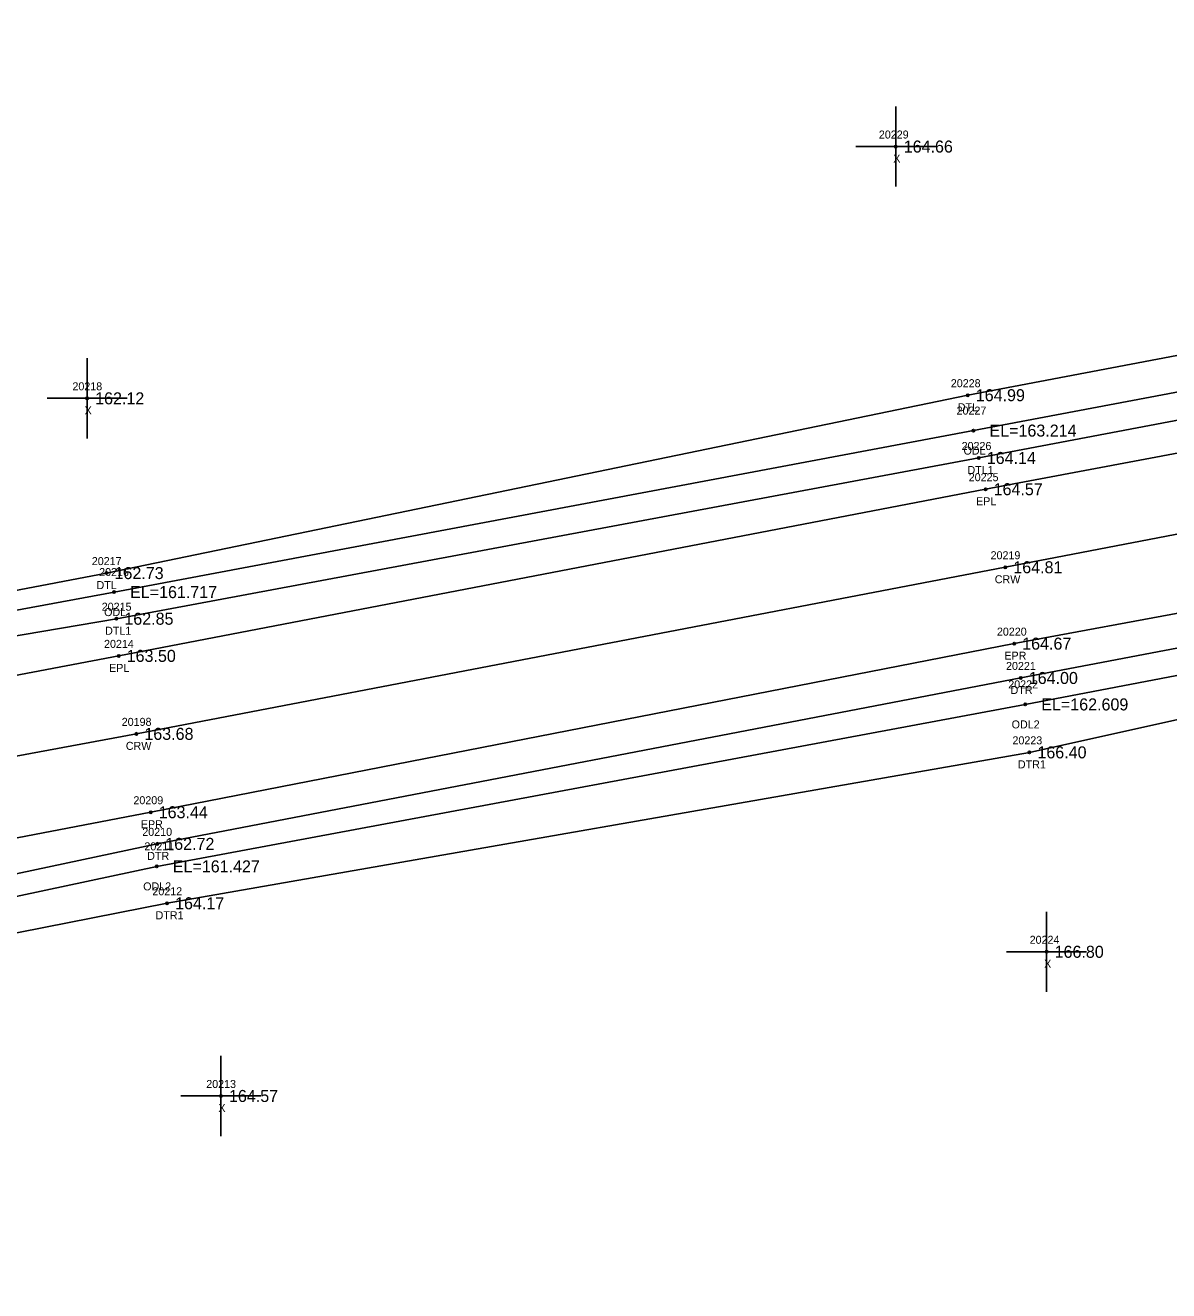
# Model space of a CAD drawing. Extents: x 2381545 to 2382928, y 1029933 to 1030589.
# Drawn here: x 2382543.8 to 2382686.7, y 1030367.7 to 1030525.8 of the extents above; entities that cross this region are included whole.
import ezdxf

# ---------------------------------------------------------------- set-up
doc = ezdxf.new("R2010")
doc.units = 0
for name, color, linetype in [('RD_DTM_BkLn1', 7, 'Continuous'), ('RD_EX_H2O', 7, 'Continuous'), ('RD_EX_H2O_txCode', 7, 'Continuous'), ('RD_EX_Misc', 7, 'Continuous'), ('RD_EX_Misc_txCode', 7, 'Continuous'), ('RD_EX_Road', 7, 'Continuous'), ('RD_EX_Road_txCode', 7, 'Continuous'), ('RD_EX_TX_H2O_ELEV', 7, 'Continuous'), ('RD_EX_TX_Misc_ELEV', 7, 'Continuous'), ('RD_EX_TX_Road_ELEV', 7, 'Continuous'), ('RD_HC_Survey_ELEV', 7, 'Continuous'), ('RD_HC_Survey_txCode', 7, 'Continuous'), ('RD_SMD_Locator', 7, 'Continuous')]:
    doc.layers.add(name, color=color, linetype=linetype)

msp = doc.modelspace()

# ---------------------------------------------------------------- linework, layer by layer
at = {"layer": 'RD_DTM_BkLn1'}
msp.add_lwpolyline([(2382237.83, 1030377.97), (2382343.9, 1030397.77), (2382436.97, 1030414.87), (2382557.72, 1030437.27), (2382666.29, 1030458.08), (2382780.92, 1030480.13), (2382908.6, 1030503.95)], dxfattribs=at)
at = {"layer": 'RD_EX_H2O'}
for points in [[(2382466.62, 1030439.12), (2382470.56, 1030441.45), (2382553.99, 1030457.35), (2382661.6, 1030479.57), (2382777.69, 1030501.62), (2382905.21, 1030525.77)], [(2382466.62, 1030439.12), (2382471.06, 1030439.47), (2382554.93, 1030454.98), (2382662.31, 1030475.15), (2382778.18, 1030497.02), (2382905.16, 1030521.52)], [(2382466.62, 1030439.12), (2382471.74, 1030437.5), (2382555.22, 1030451.65), (2382662.97, 1030471.73), (2382778.37, 1030493.62), (2382905.48, 1030518.64)], [(2382424.24, 1030390.04), (2382440.08, 1030397.96), (2382560.33, 1030423.53), (2382668.22, 1030444.25), (2382764.75, 1030462.61), (2382766.55, 1030456.54)], [(2382424.24, 1030390.04), (2382440.69, 1030395.22), (2382560.27, 1030420.72), (2382668.78, 1030440.95), (2382763.32, 1030459.02)], [(2382424.24, 1030390.04), (2382441.2, 1030392.41), (2382561.56, 1030416.11), (2382669.3, 1030434.96), (2382766.55, 1030456.54)]]:
    msp.add_lwpolyline(points, dxfattribs=at)
at = {"layer": 'RD_EX_Misc'}
for p, q in [((2382652.6, 1030505.63), (2382652.6, 1030515.63)), ((2382647.6, 1030510.63), (2382657.6, 1030510.63)), ((2382551.57, 1030474.18), (2382551.57, 1030484.18)), ((2382546.57, 1030479.18), (2382556.57, 1030479.18)), ((2382671.45, 1030405.05), (2382671.45, 1030415.05)), ((2382666.45, 1030410.05), (2382676.45, 1030410.05)), ((2382568.29, 1030387.04), (2382568.29, 1030397.04)), ((2382563.29, 1030392.04), (2382573.29, 1030392.04))]:
    msp.add_line(p, q, dxfattribs=at)
at = {"layer": 'RD_EX_Road'}
for points in [[(2382237.83, 1030377.97), (2382235.13, 1030386.42), (2382342.38, 1030406.92), (2382435.08, 1030424.16), (2382555.51, 1030447.01), (2382663.83, 1030467.83), (2382778.84, 1030489.45), (2382906.57, 1030513.81)], [(2382237.83, 1030377.97), (2382241.1, 1030367.72), (2382346.41, 1030388.08), (2382437.98, 1030404.17), (2382559.51, 1030427.48), (2382667.4, 1030448.54), (2382782.14, 1030469.8), (2382910.48, 1030494.44)]]:
    msp.add_lwpolyline(points, dxfattribs=at)
at = {"layer": 'RD_SMD_Locator'}
for centre in [(2382652.6, 1030510.63), (2382551.57, 1030479.18), (2382661.6, 1030479.57), (2382662.31, 1030475.15), (2382662.97, 1030471.73), (2382663.83, 1030467.83), (2382553.99, 1030457.35), (2382666.29, 1030458.08), (2382554.93, 1030454.98), (2382555.22, 1030451.65), (2382667.4, 1030448.54), (2382555.51, 1030447.01), (2382668.22, 1030444.25), (2382668.78, 1030440.95), (2382557.72, 1030437.27), (2382669.3, 1030434.96), (2382559.51, 1030427.48), (2382560.33, 1030423.53), (2382560.27, 1030420.72), (2382561.56, 1030416.11), (2382671.45, 1030410.05), (2382568.29, 1030392.04)]:
    msp.add_circle(centre, 0.15, dxfattribs=at)

# ---------------------------------------------------------------- texts
at = {"layer": 'RD_EX_H2O_txCode'}
for s, p in [('20228', (2382659.48, 1030480.57)), ('20227', (2382660.2, 1030477.15)), ('DTL', (2382660.35, 1030477.57)), ('20226', (2382660.83, 1030472.73)), ('ODL', (2382661.07, 1030472.15)), ('DTL1', (2382661.56, 1030469.73)), ('20217', (2382552.15, 1030458.35)), ('20216', (2382553.07, 1030456.98)), ('DTL', (2382552.74, 1030455.35)), ('20215', (2382553.39, 1030452.65)), ('ODL', (2382553.69, 1030451.98)), ('DTL1', (2382553.81, 1030449.65)), ('20221', (2382666.38, 1030445.25)), ('20222', (2382666.66, 1030442.95)), ('DTR', (2382666.95, 1030442.25)), ('ODL2', (2382667.08, 1030437.95)), ('20223', (2382667.18, 1030435.96)), ('DTR1', (2382667.86, 1030432.96)), ('20210', (2382558.46, 1030424.53)), ('20211', (2382558.72, 1030422.72)), ('DTR', (2382559.07, 1030421.53)), ('ODL2', (2382558.57, 1030417.72)), ('20212', (2382559.72, 1030417.11)), ('DTR1', (2382560.12, 1030414.11))]:
    msp.add_text(s, height=1, dxfattribs=at).set_placement(p)
at = {"layer": 'RD_EX_Misc_txCode'}
for s, p in [('20229', (2382650.49, 1030511.63)), ('X', (2382652.29, 1030508.63)), ('20218', (2382549.73, 1030480.18)), ('X', (2382551.25, 1030477.18)), ('20224', (2382669.33, 1030411.05)), ('X', (2382671.14, 1030408.05)), ('20213', (2382566.45, 1030393.04)), ('X', (2382567.97, 1030390.04))]:
    msp.add_text(s, height=1, dxfattribs=at).set_placement(p)
at = {"layer": 'RD_EX_Road_txCode'}
for s, p in [('20225', (2382661.72, 1030468.83)), ('EPL', (2382662.63, 1030465.83)), ('20220', (2382665.24, 1030449.54)), ('20214', (2382553.68, 1030448.01)), ('EPR', (2382666.17, 1030446.54)), ('EPL', (2382554.31, 1030445.01)), ('20209', (2382557.35, 1030428.48)), ('EPR', (2382558.28, 1030425.48))]:
    msp.add_text(s, height=1, dxfattribs=at).set_placement(p)
at = {"layer": 'RD_EX_TX_H2O_ELEV'}
for s, p in [('164.99', (2382662.6, 1030478.82)), ('EL=163.214', (2382664.31, 1030474.4)), ('164.14', (2382663.97, 1030470.98)), ('162.73', (2382554.99, 1030456.6)), ('EL=161.717', (2382556.93, 1030454.23)), ('162.85', (2382556.22, 1030450.9)), ('164.00', (2382669.22, 1030443.5)), ('EL=162.609', (2382670.78, 1030440.2)), ('166.40', (2382670.3, 1030434.21)), ('162.72', (2382561.33, 1030422.78)), ('EL=161.427', (2382562.27, 1030419.97)), ('164.17', (2382562.56, 1030415.36))]:
    msp.add_text(s, height=1.5, dxfattribs=at).set_placement(p)
at = {"layer": 'RD_EX_TX_Misc_ELEV'}
for s, p in [('164.66', (2382653.6, 1030509.88)), ('162.12', (2382552.57, 1030478.43)), ('166.80', (2382672.45, 1030409.3)), ('164.57', (2382569.29, 1030391.29))]:
    msp.add_text(s, height=1.5, dxfattribs=at).set_placement(p)
at = {"layer": 'RD_EX_TX_Road_ELEV'}
for s, p in [('164.57', (2382664.83, 1030467.08)), ('164.67', (2382668.4, 1030447.79)), ('163.50', (2382556.51, 1030446.26)), ('163.44', (2382560.51, 1030426.73))]:
    msp.add_text(s, height=1.5, dxfattribs=at).set_placement(p)
at = {"layer": 'RD_HC_Survey_ELEV'}
for s, p in [('164.81', (2382667.29, 1030457.33)), ('163.68', (2382558.72, 1030436.52))]:
    msp.add_text(s, height=1.5, dxfattribs=at).set_placement(p)
at = {"layer": 'RD_HC_Survey_txCode'}
for s, p in [('20219', (2382664.45, 1030459.08)), ('CRW', (2382664.97, 1030456.08)), ('20198', (2382555.89, 1030438.27)), ('CRW', (2382556.4, 1030435.27))]:
    msp.add_text(s, height=1, dxfattribs=at).set_placement(p)

doc.saveas('drawing.dxf')
